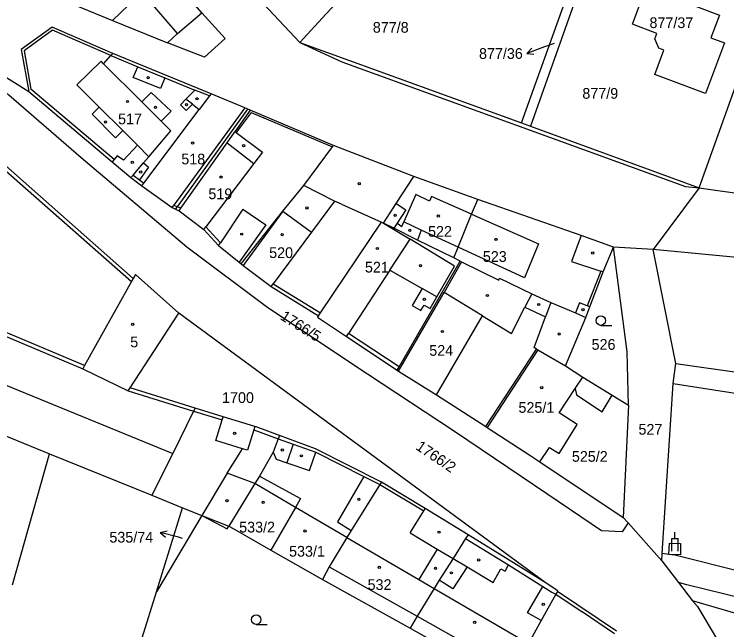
# Model space of a CAD drawing. Extents: x -724107 to -720612, y -1045267 to -1038441.
# Drawn here: x -722587.6 to -722474.4, y -1042827.7 to -1042730 of the extents above; entities that cross this region are included whole.
import ezdxf

# ---------------------------------------------------------------- set-up
doc = ezdxf.new("R2010")
doc.units = 0
for name, color, linetype in [('Hranice parcel', 7, 'Continuous'), ('Parcelní čísla', 7, 'Continuous'), ('Pop  PČ popisy', 7, 'Continuous'), ('Vnitřní kresba', 7, 'Continuous'), ('Značky budov', 7, 'Continuous'), ('Značky kultur', 7, 'Continuous')]:
    doc.layers.add(name, color=color, linetype=linetype)

msp = doc.modelspace()

# ---------------------------------------------------------------- linework, layer by layer
at = {"layer": 'Hranice parcel'}
for p, q in [((-722507.04, -1042747.25), (-722495.83, -1042716.07)), ((-722494.55, -1042716.55), (-722505.62, -1042747.77)), ((-722598.12, -1042734.3), (-722585.24, -1042742.26)), ((-722542.23, -1042734.49), (-722507.04, -1042747.25)), ((-722507.04, -1042747.25), (-722505.62, -1042747.77)), ((-722505.62, -1042747.77), (-722478.81, -1042757.57)), ((-722524.13, -1042755.76), (-722536.88, -1042750.83)), ((-722513.99, -1042759.39), (-722524.13, -1042755.76)), ((-722478.81, -1042757.57), (-722486.15, -1042767.37)), ((-722478.81, -1042757.57), (-722464.91, -1042759.58)), ((-722625.89, -1042765.65), (-722576.69, -1042786.28)), ((-722486.15, -1042767.37), (-722492.42, -1042766.95)), ((-722448.85, -1042770.94), (-722486.15, -1042767.37)), ((-722482.53, -1042785.44), (-722486.15, -1042767.37)), ((-722516.76, -1042769.18), (-722517.79, -1042768.68)), ((-722628.13, -1042772.91), (-722562.42, -1042799.69)), ((-722569.18, -1042789.29), (-722561.46, -1042777.43)), ((-722503.29, -1042820.21), (-722561.46, -1042777.43)), ((-722500.03, -1042785.83), (-722496.81, -1042778.11)), ((-722630.36, -1042780.16), (-722581.97, -1042799.76)), ((-722482.94, -1042788.61), (-722482.53, -1042785.44)), ((-722482.53, -1042785.44), (-722452.41, -1042789.78)), ((-722500.03, -1042785.83), (-722497.32, -1042787.58)), ((-722482.94, -1042788.61), (-722453.08, -1042793.31)), ((-722558.85, -1042792.5), (-722569.18, -1042789.29)), ((-722490.05, -1042792.04), (-722490.87, -1042809.87)), ((-722587.85, -1042820.56), (-722581.97, -1042799.76)), ((-722581.97, -1042799.76), (-722565.72, -1042806.34)), ((-722562.42, -1042799.69), (-722565.72, -1042806.34)), ((-722504.11, -1042801.05), (-722490.87, -1042809.87)), ((-722565.72, -1042806.34), (-722560.85, -1042808.32)), ((-722564.98, -1042821.67), (-722560.85, -1042808.32)), ((-722560.85, -1042808.32), (-722557.81, -1042809.55)), ((-722557.81, -1042809.55), (-722564.98, -1042821.67)), ((-722490.87, -1042809.87), (-722490.11, -1042810.72)), ((-722484.77, -1042816.73), (-722490.11, -1042810.72)), ((-722546.82, -1042815.05), (-722538.65, -1042819.73)), ((-722538.65, -1042819.73), (-722524.69, -1042827.43)), ((-722567.24, -1042828.98), (-722564.98, -1042821.67)), ((-722491.95, -1042827.93), (-722501.32, -1042821.59)), ((-722458.65, -1042829.29), (-722479.86, -1042823.1))]:
    msp.add_line(p, q, dxfattribs=at)
for points in [[(-722478.81, -1042757.57), (-722467.76, -1042726.65), (-722480.33, -1042721.91), (-722478.07, -1042715.93)], [(-722577.66, -1042728.69), (-722571.95, -1042731.01), (-722563.26, -1042734.55), (-722561.68, -1042733.09), (-722557.79, -1042729.77), (-722566.88, -1042719.23)], [(-722542.23, -1042734.49), (-722538.04, -1042729.97), (-722533.4, -1042724.97), (-722529.78, -1042720.98)], [(-722554.67, -1042721.34), (-722551.35, -1042724.78), (-722542.23, -1042734.49)], [(-722485.54, -1042733.05), (-722489.42, -1042731.59), (-722486.42, -1042723.6), (-722478.43, -1042726.6), (-722479.25, -1042728.78), (-722475.6, -1042730.15), (-722476.95, -1042733.75), (-722474.8, -1042734.56), (-722477.81, -1042742.58), (-722485.84, -1042739.57), (-722484.41, -1042735.74), (-722485.25, -1042735.42), (-722485.87, -1042733.91), (-722485.54, -1042733.05)], [(-722621.31, -1042730.88), (-722598.17, -1042745.93), (-722568.69, -1042771.94)], [(-722571.94, -1042736.22), (-722581.55, -1042732.06), (-722586.47, -1042735.61), (-722585.24, -1042742.26)], [(-722490.11, -1042810.72), (-722491.06, -1042812.14), (-722494.33, -1042811.98), (-722502.87, -1042806.21), (-722517.68, -1042796.22), (-722531.51, -1042787.14), (-722547.31, -1042776.62), (-722560.16, -1042766.96), (-722576.96, -1042752.81), (-722588.44, -1042742.85), (-722598.12, -1042734.3)], [(-722569.04, -1042755.93), (-722568.71, -1042755.55), (-722567.04, -1042753.61), (-722566.2, -1042752.63), (-722562.69, -1042748.51), (-722564.23, -1042746.98), (-722567.31, -1042743.92), (-722573.4, -1042737.87), (-722572.24, -1042736.56), (-722571.94, -1042736.22)], [(-722550.48, -1042745.08), (-722550.94, -1042744.89), (-722556.31, -1042742.62), (-722571.94, -1042736.22)], [(-722585.24, -1042742.26), (-722572.01, -1042753.42), (-722569.04, -1042755.93)], [(-722561.98, -1042760.97), (-722561.67, -1042760.55), (-722550.48, -1042745.08)], [(-722536.88, -1042750.83), (-722550.11, -1042745.24), (-722550.48, -1042745.08)], [(-722551.53, -1042769.61), (-722544.91, -1042761.27), (-722541.61, -1042757.2), (-722537.06, -1042751.07), (-722536.88, -1042750.83)], [(-722569.04, -1042755.93), (-722567.3, -1042757.23), (-722562.52, -1042760.7), (-722561.98, -1042760.97)], [(-722528.92, -1042763.17), (-722526.91, -1042760.07), (-722524.13, -1042755.76)], [(-722517.79, -1042768.68), (-722517.09, -1042766.97), (-722514.96, -1042761.75), (-722513.99, -1042759.39)], [(-722492.42, -1042766.95), (-722497.55, -1042765.15), (-722513.99, -1042759.39)], [(-722561.98, -1042760.97), (-722561.4, -1042761.21), (-722557.46, -1042764.15), (-722555.12, -1042766.69), (-722551.85, -1042769.35), (-722551.53, -1042769.61)], [(-722539.27, -1042777.88), (-722538.96, -1042777.42), (-722529.24, -1042763.03), (-722528.92, -1042763.17)], [(-722517.79, -1042768.68), (-722523.52, -1042765.85), (-722527.29, -1042763.98), (-722528.92, -1042763.17)], [(-722496.81, -1042778.11), (-722496.17, -1042776.44), (-722494.04, -1042770.91), (-722492.42, -1042766.95)], [(-722490.05, -1042792.04), (-722490.25, -1042783.61), (-722492.42, -1042766.95)], [(-722551.53, -1042769.61), (-722551.23, -1042769.9), (-722546.79, -1042773.23), (-722539.27, -1042777.88)], [(-722526.76, -1042786.49), (-722526.46, -1042785.97), (-722516.76, -1042769.18)], [(-722516.76, -1042769.18), (-722516.54, -1042769.29), (-722510.64, -1042772.21), (-722510.55, -1042771.9), (-722505.38, -1042774.36), (-722502.37, -1042775.77), (-722498.46, -1042777.42), (-722496.81, -1042778.11)], [(-722568.69, -1042771.94), (-722568.96, -1042772.42), (-722576.4, -1042785.76), (-722576.69, -1042786.28)], [(-722561.46, -1042777.43), (-722568.33, -1042771.29), (-722568.69, -1042771.94)], [(-722539.27, -1042777.88), (-722539.42, -1042778.08), (-722534.8, -1042781.15), (-722526.76, -1042786.49)], [(-722512.69, -1042795.44), (-722504.64, -1042783.15), (-722504.42, -1042783.28), (-722500.03, -1042785.83)], [(-722576.69, -1042786.28), (-722569.48, -1042789.75), (-722569.18, -1042789.29)], [(-722526.76, -1042786.49), (-722526.55, -1042786.63), (-722520.53, -1042790.4), (-722512.69, -1042795.44)], [(-722504.11, -1042801.05), (-722502.6, -1042798.74), (-722501.06, -1042799.7), (-722498.21, -1042795.1), (-722501.04, -1042793.25), (-722498.5, -1042789.38), (-722497.32, -1042787.58)], [(-722497.32, -1042787.58), (-722492.63, -1042790.46), (-722490.05, -1042792.04)], [(-722484.77, -1042816.73), (-722484.69, -1042815.57), (-722482.94, -1042788.61)], [(-722558.85, -1042792.5), (-722559.09, -1042792.98), (-722562.42, -1042799.69)], [(-722545.47, -1042796.85), (-722549.18, -1042795.5), (-722549.39, -1042795.43), (-722554.4, -1042793.88), (-722558.85, -1042792.5)], [(-722512.69, -1042795.44), (-722512.48, -1042795.58), (-722505.53, -1042800.1), (-722504.11, -1042801.05)], [(-722545.47, -1042796.85), (-722545.66, -1042797.37), (-722546.44, -1042799.51), (-722548.66, -1042803.29), (-722542.14, -1042806.88), (-722542.93, -1042808.26), (-722546.82, -1042815.05)], [(-722529.27, -1042804.24), (-722539.73, -1042798.95), (-722545.47, -1042796.85)], [(-722529.27, -1042804.24), (-722529.51, -1042804.62), (-722534.07, -1042811.92), (-722534.78, -1042813.05), (-722537.59, -1042817.71), (-722538.65, -1042819.73)], [(-722515.52, -1042812.62), (-722522.33, -1042808.42), (-722529.27, -1042804.24)], [(-722557.81, -1042809.55), (-722553.76, -1042811.66), (-722553.51, -1042811.22), (-722552.81, -1042811.62), (-722546.82, -1042815.05)], [(-722515.52, -1042812.62), (-722515.9, -1042813.21), (-722517.9, -1042816.37), (-722520.1, -1042819.84), (-722520.92, -1042821.12), (-722523.62, -1042825.53), (-722524.69, -1042827.43)], [(-722503.29, -1042820.21), (-722509.4, -1042816.38), (-722515.52, -1042812.62)], [(-722484.77, -1042816.73), (-722482.08, -1042820.21), (-722479.86, -1042823.1)], [(-722501.32, -1042821.59), (-722501.25, -1042821.5), (-722503.29, -1042820.21)], [(-722501.32, -1042821.59), (-722501.56, -1042822.03), (-722503.9, -1042826.22), (-722505.92, -1042829.85), (-722508.32, -1042834.06)], [(-722479.86, -1042823.1), (-722479.07, -1042823.99), (-722468.38, -1042842)], [(-722524.69, -1042827.43), (-722509.43, -1042836.01), (-722508.32, -1042834.06)]]:
    msp.add_lwpolyline(points, dxfattribs=at)
at = {"layer": 'Pop  PČ popisy'}
for p, q in [((-722501.86, -1042734.64), (-722503.36, -1042735.2)), ((-722503.36, -1042735.2), (-722506.18, -1042736.23)), ((-722506.18, -1042736.23), (-722505.41, -1042735.41)), ((-722506.18, -1042736.23), (-722505.07, -1042736.35)), ((-722564.4, -1042812.23), (-722563.3, -1042812.01)), ((-722561.5, -1042813.01), (-722564.4, -1042812.23)), ((-722564.4, -1042812.23), (-722563.56, -1042812.98)), ((-722560.84, -1042813.18), (-722561.5, -1042813.01))]:
    msp.add_line(p, q, dxfattribs=at)
at = {"layer": 'Vnitřní kresba'}
for p, q in [((-722567.29, -1042726.49), (-722571.95, -1042731.01)), ((-722561.68, -1042733.09), (-722567.29, -1042726.49)), ((-722557.79, -1042729.77), (-722554.11, -1042733.85)), ((-722581.5, -1042732.57), (-722585.98, -1042735.8)), ((-722572.24, -1042736.56), (-722581.5, -1042732.57)), ((-722557.38, -1042736.85), (-722563.26, -1042734.55)), ((-722554.11, -1042733.85), (-722557.38, -1042736.85)), ((-722542.23, -1042734.49), (-722535.56, -1042737.58)), ((-722585.98, -1042735.8), (-722584.95, -1042741.92)), ((-722572.24, -1042736.56), (-722567.97, -1042738.35)), ((-722573.79, -1042737.48), (-722577.62, -1042741.22)), ((-722573.4, -1042737.87), (-722573.79, -1042737.48)), ((-722535.56, -1042737.58), (-722481.01, -1042757.33)), ((-722568.68, -1042740.06), (-722567.97, -1042738.35)), ((-722567.97, -1042738.35), (-722563.67, -1042740.12)), ((-722564.36, -1042741.82), (-722568.68, -1042740.06)), ((-722563.67, -1042740.12), (-722564.36, -1042741.82)), ((-722563.67, -1042740.12), (-722558.9, -1042742.09)), ((-722577.62, -1042741.22), (-722574.09, -1042744.74)), ((-722571.72, -1042753.08), (-722584.95, -1042741.92)), ((-722567.31, -1042743.92), (-722565.84, -1042742.43)), ((-722565.84, -1042742.43), (-722562.64, -1042745.37)), ((-722558.9, -1042742.09), (-722560.31, -1042743.51)), ((-722556.58, -1042742.98), (-722558.9, -1042742.09)), ((-722556.31, -1042742.62), (-722556.58, -1042742.98)), ((-722561.17, -1042744.38), (-722560.31, -1042743.51)), ((-722559.28, -1042744.29), (-722560.31, -1042743.51)), ((-722556.58, -1042742.98), (-722558.19, -1042745.11)), ((-722574.09, -1042744.74), (-722575.2, -1042745.85)), ((-722574.09, -1042744.74), (-722570.36, -1042748.47)), ((-722550.94, -1042744.89), (-722562.22, -1042760.3)), ((-722561.17, -1042744.38), (-722560.26, -1042745.28)), ((-722560.26, -1042745.28), (-722559.28, -1042744.29)), ((-722559.28, -1042744.29), (-722558.19, -1042745.11)), ((-722575.2, -1042745.85), (-722571.51, -1042749.62)), ((-722567, -1042756.83), (-722558.19, -1042745.11)), ((-722562.64, -1042745.37), (-722564.23, -1042746.98)), ((-722550.11, -1042745.24), (-722552.53, -1042748.66)), ((-722549.95, -1042745.63), (-722552.35, -1042748.79)), ((-722549.95, -1042745.63), (-722537.06, -1042751.07)), ((-722598.5, -1042746.43), (-722568.96, -1042772.42)), ((-722571.51, -1042749.62), (-722570.36, -1042748.47)), ((-722568.03, -1042750.8), (-722570.36, -1042748.47)), ((-722553.78, -1042750.43), (-722552.53, -1042748.66)), ((-722552.35, -1042748.79), (-722552.53, -1042748.66)), ((-722552.35, -1042748.79), (-722548.15, -1042751.92)), ((-722561.11, -1042760.8), (-722553.78, -1042750.43)), ((-722553.78, -1042750.43), (-722549.51, -1042753.7)), ((-722568.03, -1042750.8), (-722570.22, -1042753.17)), ((-722566.2, -1042752.63), (-722568.03, -1042750.8)), ((-722571.21, -1042752.47), (-722571.72, -1042753.08)), ((-722570.22, -1042753.17), (-722571.21, -1042752.47)), ((-722548.15, -1042751.92), (-722549.51, -1042753.7)), ((-722571.72, -1042753.08), (-722572.01, -1042753.42)), ((-722567.04, -1042753.61), (-722566.27, -1042754.27)), ((-722549.51, -1042753.7), (-722557.16, -1042763.75)), ((-722566.27, -1042754.27), (-722567.71, -1042756.3)), ((-722568.71, -1042755.55), (-722567.71, -1042756.3)), ((-722567.71, -1042756.3), (-722567, -1042756.83)), ((-722567.3, -1042757.23), (-722567, -1042756.83)), ((-722536.71, -1042759.66), (-722541.61, -1042757.2)), ((-722481.01, -1042757.33), (-722478.81, -1042757.57)), ((-722523.83, -1042758.63), (-722525.74, -1042762.98)), ((-722521.64, -1042759.67), (-722523.83, -1042758.63)), ((-722521.32, -1042758.94), (-722521.64, -1042759.67)), ((-722514.96, -1042761.75), (-722521.32, -1042758.94)), ((-722562.52, -1042760.7), (-722562.22, -1042760.3)), ((-722562.22, -1042760.3), (-722561.67, -1042760.55)), ((-722561.11, -1042760.8), (-722561.67, -1042760.55)), ((-722536.71, -1042759.66), (-722540.38, -1042764.59)), ((-722535.63, -1042760.15), (-722536.71, -1042759.66)), ((-722535.63, -1042760.15), (-722529.24, -1042763.03)), ((-722526.91, -1042760.07), (-722525.38, -1042761.06)), ((-722561.4, -1042761.21), (-722561.11, -1042760.8)), ((-722551.27, -1042760.97), (-722554.84, -1042766.28)), ((-722551.27, -1042760.97), (-722547.64, -1042763.41)), ((-722544.91, -1042761.27), (-722551.23, -1042769.9)), ((-722544.91, -1042761.27), (-722540.38, -1042764.59)), ((-722525.38, -1042761.06), (-722526.75, -1042763.16)), ((-722514.96, -1042761.75), (-722504.35, -1042766.44)), ((-722526.06, -1042763.71), (-722525.74, -1042762.98)), ((-722522.97, -1042764.26), (-722525.74, -1042762.98)), ((-722557.46, -1042764.15), (-722557.16, -1042763.75)), ((-722557.16, -1042763.75), (-722554.84, -1042766.28)), ((-722547.64, -1042763.41), (-722551.85, -1042769.35)), ((-722528.92, -1042763.17), (-722524.7, -1042765.73)), ((-722526.75, -1042763.16), (-722527.29, -1042763.98)), ((-722526.75, -1042763.16), (-722526.06, -1042763.71)), ((-722576.4, -1042785.76), (-722625.71, -1042765.08)), ((-722540.38, -1042764.59), (-722546.47, -1042772.79)), ((-722522.97, -1042764.26), (-722523.52, -1042765.85)), ((-722517.09, -1042766.97), (-722522.97, -1042764.26)), ((-722497.55, -1042765.15), (-722499.1, -1042769.24)), ((-722555.12, -1042766.69), (-722554.84, -1042766.28)), ((-722527.92, -1042770.65), (-722524.7, -1042765.73)), ((-722517.68, -1042769.99), (-722524.7, -1042765.73)), ((-722506.56, -1042771.82), (-722517.09, -1042766.97)), ((-722504.35, -1042766.44), (-722506.56, -1042771.82)), ((-722516.54, -1042769.29), (-722519.32, -1042774.18)), ((-722499.1, -1042769.24), (-722494.46, -1042770.77)), ((-722527.92, -1042770.65), (-722534.5, -1042780.69)), ((-722527.92, -1042770.65), (-722522.83, -1042773.52)), ((-722520.48, -1042774.85), (-722517.68, -1042769.99)), ((-722494.46, -1042770.77), (-722496.59, -1042776.27)), ((-722494.04, -1042770.91), (-722494.46, -1042770.77)), ((-722546.79, -1042773.23), (-722546.47, -1042772.79)), ((-722546.47, -1042772.79), (-722538.96, -1042777.42)), ((-722526.55, -1042786.63), (-722519.32, -1042774.18)), ((-722522.83, -1042773.52), (-722524.37, -1042776.25)), ((-722520.48, -1042774.85), (-722522.83, -1042773.52)), ((-722513.21, -1042777.88), (-722519.32, -1042774.18)), ((-722521.53, -1042776.71), (-722520.48, -1042774.85)), ((-722505.38, -1042774.36), (-722506.49, -1042776.52)), ((-722524.37, -1042776.25), (-722523.04, -1042777)), ((-722523.04, -1042777), (-722522.49, -1042776.17)), ((-722522.49, -1042776.17), (-722521.53, -1042776.71)), ((-722508.62, -1042780.66), (-722506.49, -1042776.52)), ((-722506.49, -1042776.52), (-722503.2, -1042778.01)), ((-722502.37, -1042775.77), (-722503.2, -1042778.01)), ((-722497.84, -1042775.79), (-722498.46, -1042777.42)), ((-722496.59, -1042776.27), (-722497.84, -1042775.79)), ((-722496.17, -1042776.44), (-722496.59, -1042776.27)), ((-722520.53, -1042790.4), (-722513.21, -1042777.88)), ((-722513.21, -1042777.88), (-722508.62, -1042780.66)), ((-722505.03, -1042782.92), (-722503.2, -1042778.01)), ((-722534.8, -1042781.15), (-722534.5, -1042780.69)), ((-722526.46, -1042785.97), (-722534.5, -1042780.69)), ((-722504.42, -1042783.28), (-722512.48, -1042795.58)), ((-722504.64, -1042783.15), (-722505.03, -1042782.92)), ((-722569.48, -1042789.75), (-722559.09, -1042792.98)), ((-722498.5, -1042789.38), (-722498.28, -1042790.42)), ((-722498.28, -1042790.42), (-722494.25, -1042793.1)), ((-722494.25, -1042793.1), (-722492.63, -1042790.46)), ((-722559.09, -1042792.98), (-722554.56, -1042794.39)), ((-722555.57, -1042797.63), (-722554.56, -1042794.39)), ((-722554.56, -1042794.39), (-722554.4, -1042793.88)), ((-722549.39, -1042795.43), (-722549.55, -1042795.95)), ((-722549.55, -1042795.95), (-722550.56, -1042799.19)), ((-722549.55, -1042795.95), (-722545.66, -1042797.37)), ((-722551.34, -1042798.95), (-722555.57, -1042797.63)), ((-722545.66, -1042797.37), (-722543.28, -1042798.24)), ((-722553.77, -1042802.81), (-722551.34, -1042798.95)), ((-722550.56, -1042799.19), (-722551.34, -1042798.95)), ((-722543.28, -1042798.24), (-722544.3, -1042801.19)), ((-722543.28, -1042798.24), (-722539.67, -1042799.49)), ((-722546.44, -1042799.51), (-722545.97, -1042800.62)), ((-722540.68, -1042802.42), (-722539.67, -1042799.49)), ((-722539.67, -1042799.49), (-722532.06, -1042803.34)), ((-722545.97, -1042800.62), (-722544.3, -1042801.19)), ((-722544.3, -1042801.19), (-722540.68, -1042802.42)), ((-722553.77, -1042802.81), (-722557.81, -1042809.55)), ((-722549.36, -1042804.48), (-722553.77, -1042802.81)), ((-722548.66, -1042803.29), (-722549.36, -1042804.48)), ((-722532.06, -1042803.34), (-722536.27, -1042810.55)), ((-722532.06, -1042803.34), (-722529.51, -1042804.62)), ((-722549.36, -1042804.48), (-722553.51, -1042811.22)), ((-722542.93, -1042808.26), (-722549.36, -1042804.48)), ((-722529.51, -1042804.62), (-722522.56, -1042808.8)), ((-722534.78, -1042813.05), (-722542.93, -1042808.26)), ((-722524.7, -1042812.31), (-722522.56, -1042808.8)), ((-722522.56, -1042808.8), (-722522.33, -1042808.42)), ((-722557.81, -1042809.55), (-722553.51, -1042811.22)), ((-722536.27, -1042810.55), (-722534.07, -1042811.92)), ((-722524.7, -1042812.31), (-722520.43, -1042814.92)), ((-722534.78, -1042813.05), (-722523.35, -1042819.7)), ((-722515.9, -1042813.21), (-722509.08, -1042817.4)), ((-722520.43, -1042814.92), (-722523.35, -1042819.7)), ((-722520.43, -1042814.92), (-722517.9, -1042816.37)), ((-722483.63, -1042815.73), (-722483.55, -1042813.94)), ((-722483.55, -1042813.94), (-722481.78, -1042814.02)), ((-722481.78, -1042814.02), (-722481.78, -1042815.81)), ((-722483.63, -1042815.73), (-722484.69, -1042815.57)), ((-722482.71, -1042815.87), (-722483.63, -1042815.73)), ((-722481.78, -1042815.81), (-722483.63, -1042815.73)), ((-722457.33, -1042822.16), (-722482.71, -1042815.87)), ((-722517.9, -1042816.37), (-722515.68, -1042817.7)), ((-722537.59, -1042817.71), (-722523.62, -1042825.53)), ((-722515.68, -1042817.7), (-722517.95, -1042821.2)), ((-722515.68, -1042817.7), (-722511.54, -1042820.17)), ((-722511.54, -1042820.17), (-722510.33, -1042818.01)), ((-722510.33, -1042818.01), (-722509.64, -1042818.4)), ((-722509.64, -1042818.4), (-722509.08, -1042817.4)), ((-722509.08, -1042817.4), (-722503.66, -1042820.8)), ((-722523.35, -1042819.7), (-722520.92, -1042821.12)), ((-722517.95, -1042821.2), (-722520.1, -1042819.84)), ((-722480.77, -1042820.54), (-722482.08, -1042820.21)), ((-722458.05, -1042826.17), (-722480.77, -1042820.54)), ((-722520.92, -1042821.12), (-722505.92, -1042829.85)), ((-722506.08, -1042825.01), (-722503.66, -1042820.8)), ((-722503.66, -1042820.8), (-722502.21, -1042821.72)), ((-722502.21, -1042821.72), (-722501.56, -1042822.03)), ((-722501.56, -1042822.03), (-722497.42, -1042824.84)), ((-722503.9, -1042826.22), (-722506.08, -1042825.01)), ((-722492.27, -1042828.31), (-722497.42, -1042824.84)), ((-722523.62, -1042825.53), (-722508.32, -1042834.06))]:
    msp.add_line(p, q, dxfattribs=at)
at = {"layer": 'Značky budov'}
for centre in [(-722566.32, -1042740.08), (-722569.59, -1042743.87), (-722558.57, -1042743.43), (-722565.15, -1042744.78), (-722560.22, -1042744.37), (-722573.09, -1042747.11), (-722559.25, -1042750.46), (-722551.16, -1042750.88), (-722568.84, -1042753.51), (-722567.5, -1042755.06), (-722554.73, -1042755.86), (-722532.8, -1042756.91), (-722541.08, -1042760.76), (-722527.09, -1042761.91), (-722520.24, -1042762.04), (-722524.76, -1042764.3), (-722551.45, -1042764.91), (-722545.03, -1042765), (-722511.08, -1042765.75), (-722529.92, -1042767.18), (-722495.73, -1042767.91), (-722523.07, -1042769.92), (-722522.45, -1042775.26), (-722512.45, -1042774.65), (-722504.29, -1042776.08), (-722497.28, -1042776.88), (-722568.77, -1042779.21), (-722519.6, -1042780.36), (-722501.05, -1042780.75), (-722503.83, -1042789.27), (-722552.58, -1042796.5), (-722545.02, -1042799.17), (-722541.99, -1042800.09), (-722553.81, -1042807.2), (-722532.87, -1042806.99), (-722548.06, -1042807.46), (-722541.4, -1042812.01), (-722520.14, -1042812.2), (-722513.84, -1042816.6), (-722529.62, -1042817.78), (-722520.69, -1042817.93), (-722518.17, -1042818.65), (-722503.58, -1042823.65), (-722514.46, -1042826.51)]:
    msp.add_circle(centre, 0.175, dxfattribs=at)
at = {"layer": 'Značky kultur'}
for p, q in [((-722494.44, -1042779.38), (-722492.69, -1042779.38)), ((-722482.67, -1042813.2), (-722482.67, -1042812.2)), ((-722483.17, -1042813.2), (-722482.17, -1042813.2)), ((-722483.17, -1042815.2), (-722483.17, -1042813.2)), ((-722482.17, -1042815.2), (-722482.17, -1042813.2)), ((-722549.16, -1042826.83), (-722547.41, -1042826.83))]:
    msp.add_line(p, q, dxfattribs=at)
for centre in [(-722494.44, -1042778.63), (-722549.16, -1042826.08)]:
    msp.add_circle(centre, 0.75, dxfattribs=at)

# ---------------------------------------------------------------- texts
at = {"layer": 'Parcelní čísla'}
for s, p in [('877/8', (-722530.64, -1042732.95)), ('877/37', (-722486.71, -1042732.21)), ('877/36', (-722513.78, -1042737.1)), ('877/9', (-722497.37, -1042743.42)), ('517', (-722571.09, -1042747.48)), ('518', (-722561.05, -1042753.84)), ('519', (-722556.75, -1042759.36)), ('522', (-722521.87, -1042765.32)), ('520', (-722547.1, -1042768.7)), ('523', (-722513.17, -1042769.31)), ('521', (-722531.89, -1042771)), ('5', (-722569.16, -1042782.87)), ('526', (-722495.9, -1042783.26)), ('524', (-722521.68, -1042784.21)), ('1700', (-722554.58, -1042791.7)), ('525/1', (-722507.51, -1042793.26)), ('527', (-722488.46, -1042796.73)), ('525/2', (-722499.03, -1042801.03)), ('533/2', (-722551.86, -1042812.25)), ('535/74', (-722572.47, -1042813.85)), ('533/1', (-722543.94, -1042816.08)), ('532', (-722531.47, -1042821.37))]:
    msp.add_text(s, height=1.7, dxfattribs=at).set_placement(p)
for s, rotation, p in [('1766/5', 328, (-722545.46, -1042778.36)), ('1766/2', 326, (-722523.95, -1042798.97))]:
    msp.add_text(s, height=1.7, rotation=rotation, dxfattribs=at).set_placement(p)

doc.saveas('drawing.dxf')
